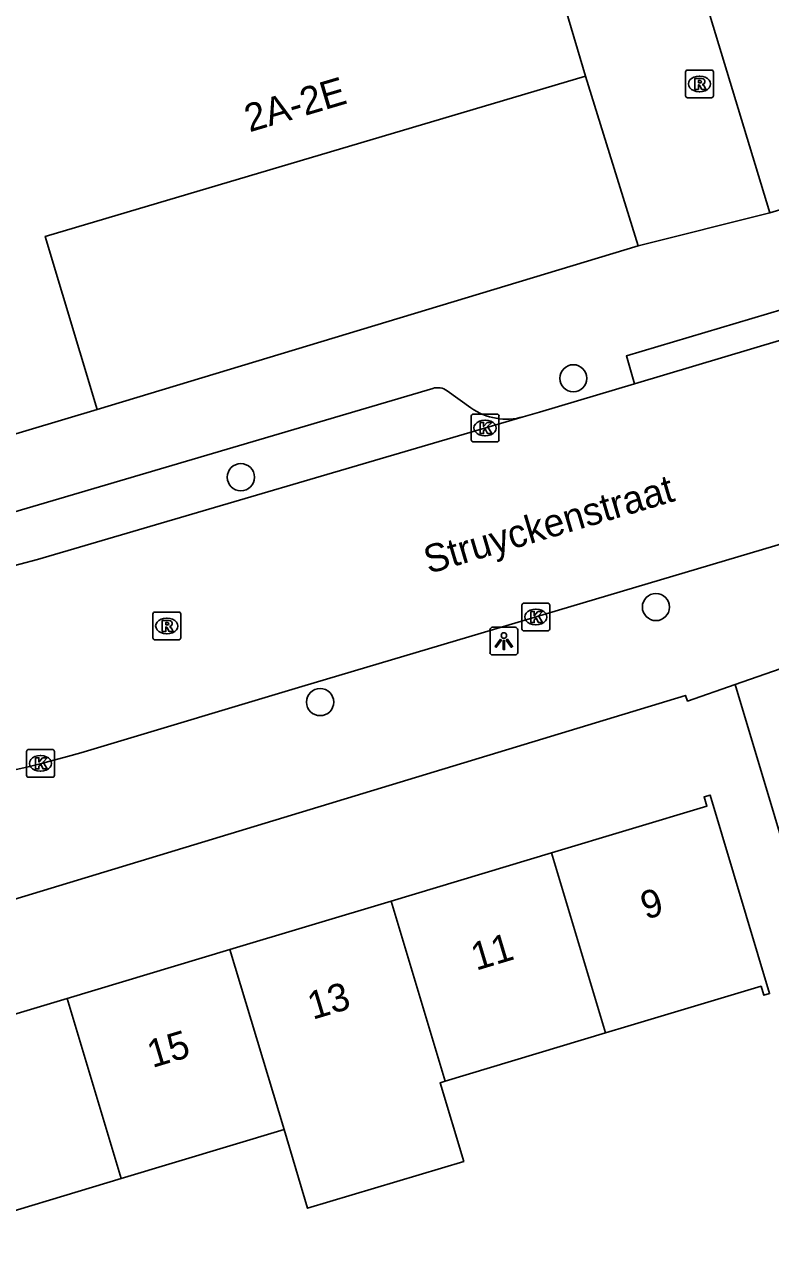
# Model space of a CAD drawing. Extents: x 158087 to 159494, y 382905 to 383981.
# Drawn here: x 158923.32 to 158950.15, y 383337.43 to 383381.71 of the extents above; entities that cross this region are included whole.
import ezdxf

# ---------------------------------------------------------------- set-up
doc = ezdxf.new("R2010")
doc.units = 0
for name, color, linetype in [('IMGEO_Boom', 7, 'Continuous'), ('IMGEO_Kolk', 7, 'Continuous'), ('IMGEO_Lichtpunt', 7, 'Continuous'), ('IMGEO_Openbare_ruimte_label', 7, 'Continuous'), ('IMGEO_Pand', 7, 'Continuous'), ('IMGEO_Pand_nummerreeks', 7, 'Continuous'), ('IMGEO_Rijbaan_lokaal_open', 7, 'Continuous'), ('IMGEO_Rioolput', 7, 'Continuous'), ('IMGEO_Voetpad_open', 7, 'Continuous')]:
    doc.layers.add(name, color=color, linetype=linetype)

msp = doc.modelspace()

# ---------------------------------------------------------------- linework, layer by layer
at = {"layer": 'IMGEO_Boom'}
for centre in [(158943.061, 383368.996), (158931.099, 383365.439), (158946.033, 383360.773), (158933.949, 383357.357)]:
    msp.add_circle(centre, 0.489, dxfattribs=at)
at = {"layer": 'IMGEO_Kolk'}
for p, q in [((158939.385, 383366.785), (158939.385, 383367.637)), ((158939.46, 383367.711), (158940.312, 383367.711)), ((158939.873, 383367.491), (158939.898, 383367.491)), ((158940.386, 383367.637), (158940.386, 383366.785)), ((158939.896, 383366.931), (158939.871, 383366.931)), ((158940.312, 383366.711), (158939.46, 383366.711)), ((158941.211, 383359.988), (158941.211, 383360.84)), ((158941.286, 383360.914), (158942.138, 383360.914)), ((158941.699, 383360.694), (158941.724, 383360.694)), ((158942.212, 383360.84), (158942.212, 383359.988)), ((158942.138, 383359.914), (158941.286, 383359.914)), ((158941.722, 383360.134), (158941.697, 383360.134)), ((158923.389, 383354.726), (158923.389, 383355.578)), ((158923.464, 383355.652), (158924.316, 383355.652)), ((158923.877, 383355.432), (158923.902, 383355.432)), ((158924.39, 383355.578), (158924.39, 383354.726)), ((158924.316, 383354.652), (158923.464, 383354.652)), ((158923.9, 383354.872), (158923.875, 383354.872))]:
    msp.add_line(p, q, dxfattribs=at)
for points in [[(158939.385, 383366.785), (158939.385, 383367.637)], [(158939.46, 383367.711), (158940.312, 383367.711)], [(158939.706, 383367.411), (158939.829, 383367.411), (158939.829, 383367.26), (158939.959, 383367.411), (158940.123, 383367.411), (158939.977, 383367.26), (158940.13, 383367.011), (158939.978, 383367.011), (158939.893, 383367.175), (158939.829, 383367.108), (158939.829, 383367.011), (158939.706, 383367.011), (158939.706, 383367.411)], [(158940.386, 383367.637), (158940.386, 383366.785)], [(158940.312, 383366.711), (158939.46, 383366.711)], [(158941.211, 383359.988), (158941.211, 383360.84)], [(158941.286, 383360.914), (158942.138, 383360.914)], [(158942.212, 383360.84), (158942.212, 383359.988)], [(158941.532, 383360.614), (158941.655, 383360.614), (158941.655, 383360.463), (158941.785, 383360.614), (158941.949, 383360.614), (158941.803, 383360.463), (158941.956, 383360.214), (158941.804, 383360.214), (158941.719, 383360.378), (158941.655, 383360.311), (158941.655, 383360.214), (158941.532, 383360.214), (158941.532, 383360.614)], [(158942.138, 383359.914), (158941.286, 383359.914)], [(158923.389, 383354.726), (158923.389, 383355.578)], [(158923.464, 383355.652), (158924.316, 383355.652)], [(158924.39, 383355.578), (158924.39, 383354.726)], [(158923.71, 383355.352), (158923.833, 383355.352), (158923.833, 383355.201), (158923.963, 383355.352), (158924.127, 383355.352), (158923.981, 383355.201), (158924.134, 383354.952), (158923.982, 383354.952), (158923.897, 383355.116), (158923.833, 383355.049), (158923.833, 383354.952), (158923.71, 383354.952), (158923.71, 383355.352)], [(158924.316, 383354.652), (158923.464, 383354.652)]]:
    msp.add_lwpolyline(points, dxfattribs=at)
for centre, start, end in [((158939.462, 383367.635), 91.552, 178.448), ((158939.462, 383367.635), 91.552, 178.448), ((158940.31, 383367.635), 1.552, 88.448), ((158940.31, 383367.635), 1.552, 88.448), ((158939.462, 383366.787), 181.552, 268.448), ((158939.462, 383366.787), 181.552, 268.448), ((158940.31, 383366.787), 271.552, 358.448), ((158940.31, 383366.787), 271.552, 358.448), ((158941.288, 383360.838), 91.552, 178.448), ((158941.288, 383360.838), 91.552, 178.448), ((158942.136, 383360.838), 1.552, 88.448), ((158942.136, 383360.838), 1.552, 88.448), ((158941.288, 383359.99), 181.552, 268.448), ((158941.288, 383359.99), 181.552, 268.448), ((158942.136, 383359.99), 271.552, 358.448), ((158942.136, 383359.99), 271.552, 358.448), ((158923.466, 383355.576), 91.552, 178.448), ((158923.466, 383355.576), 91.552, 178.448), ((158924.314, 383355.576), 1.552, 88.448), ((158924.314, 383355.576), 1.552, 88.448), ((158923.466, 383354.728), 181.552, 268.448), ((158923.466, 383354.728), 181.552, 268.448), ((158924.314, 383354.728), 271.552, 358.448), ((158924.314, 383354.728), 271.552, 358.448)]:
    msp.add_arc(centre, 0.0765, start, end, dxfattribs=at)
for centre, major_axis, ratio, start_param, end_param in [((158939.872, 383367.211), (-0.387, 0.002), 0.722429, 4.712389, 7.853982), ((158939.897, 383367.211), (-0.39, 0.002), 0.717154, 1.570796, 4.712389), ((158941.698, 383360.414), (-0.387, 0.002), 0.722429, 4.712389, 7.853982), ((158941.723, 383360.414), (-0.39, 0.002), 0.717154, 1.570796, 4.712389), ((158923.876, 383355.152), (-0.387, 0.002), 0.722429, 4.712389, 7.853982), ((158923.901, 383355.152), (-0.39, 0.002), 0.717154, 1.570796, 4.712389)]:
    msp.add_ellipse(centre, major_axis=major_axis, ratio=ratio, start_param=start_param, end_param=end_param, dxfattribs=at)
at = {"layer": 'IMGEO_Lichtpunt'}
for p, q in [((158940.063, 383359.951), (158940.063, 383359.144)), ((158940.063, 383359.951), (158940.063, 383359.144)), ((158940.965, 383360.046), (158940.157, 383360.046)), ((158940.965, 383360.046), (158940.157, 383360.046)), ((158941.059, 383359.144), (158941.059, 383359.951)), ((158941.059, 383359.144), (158941.059, 383359.951)), ((158940.157, 383359.05), (158940.965, 383359.05)), ((158940.157, 383359.05), (158940.965, 383359.05))]:
    msp.add_line(p, q, dxfattribs=at)
for points in [[(158940.437, 383359.615), (158940.476, 383359.587), (158940.288, 383359.325), (158940.25, 383359.352), (158940.437, 383359.615)], [(158940.539, 383359.567), (158940.586, 383359.567), (158940.586, 383359.245), (158940.539, 383359.245), (158940.539, 383359.567)], [(158940.649, 383359.587), (158940.687, 383359.614), (158940.874, 383359.352), (158940.835, 383359.324), (158940.649, 383359.587)]]:
    msp.add_lwpolyline(points, dxfattribs=at)
msp.add_circle((158940.562, 383359.749), 0.0994, dxfattribs=at)
for centre, start, end in [((158940.157, 383359.951), 90, 180), ((158940.157, 383359.951), 90, 180), ((158940.965, 383359.951), 0, 90), ((158940.965, 383359.951), 0, 90), ((158940.157, 383359.144), 180, 270), ((158940.157, 383359.144), 180, 270), ((158940.965, 383359.144), 270, 0), ((158940.965, 383359.144), 270, 360)]:
    msp.add_arc(centre, 0.0946, start, end, dxfattribs=at)
at = {"layer": 'IMGEO_Pand'}
for points in [[(158939.766, 383392.44), (158943.494, 383379.853)], [(158943.494, 383379.853), (158924.06, 383374.095), (158925.931, 383367.872)], [(158925.931, 383367.872), (158920.898, 383366.383)], [(158944.22, 383345.462), (158945.027, 383345.704), (158949.815, 383347.142), (158949.912, 383346.816), (158950.122, 383346.879), (158947.978, 383354.013), (158947.768, 383353.95), (158947.869, 383353.615), (158942.276, 383351.935)], [(158942.276, 383351.935), (158936.511, 383350.204)], [(158942.276, 383351.935), (158944.22, 383345.462)], [(158936.511, 383350.204), (158930.706, 383348.461)], [(158938.455, 383343.73), (158936.511, 383350.204)], [(158930.706, 383348.461), (158924.849, 383346.702)], [(158932.651, 383341.987), (158930.706, 383348.461)], [(158924.849, 383346.702), (158919.041, 383344.958)], [(158924.849, 383346.702), (158926.794, 383340.229)], [(158938.455, 383343.73), (158944.22, 383345.462)], [(158932.651, 383341.987), (158933.502, 383339.156), (158939.116, 383340.842), (158938.266, 383343.673), (158938.455, 383343.73)], [(158926.794, 383340.229), (158932.651, 383341.987)], [(158920.986, 383338.484), (158926.794, 383340.229)]]:
    msp.add_lwpolyline(points, dxfattribs=at)
at = {"layer": 'IMGEO_Rijbaan_lokaal_open'}
for points in [[(158942.233, 383428.468), (158944.391, 383393.87), (158950.13, 383374.942)], [(158943.494, 383379.853), (158945.392, 383373.761)], [(158950.13, 383374.942), (158945.392, 383373.761)], [(158980.272, 383371.894), (158974.99, 383370.288), (158953.096, 383363.795), (158933.294, 383357.916), (158925.825, 383355.673)], [(158953.723, 383371.321), (158945.266, 383368.803)], [(158941.259, 383367.613), (158941.839, 383367.783), (158945.266, 383368.803)], [(158919.464, 383361.557), (158921.866, 383361.978), (158923.788, 383362.481), (158941.259, 383367.613)]]:
    msp.add_lwpolyline(points, dxfattribs=at)
msp.add_arc((158912.536, 383400.116), 46.387, 266.7816, 286.6469, dxfattribs=at)
at = {"layer": 'IMGEO_Rioolput'}
for p, q in [((158947.099, 383379.154), (158947.099, 383380.006)), ((158947.174, 383380.08), (158948.026, 383380.08)), ((158947.587, 383379.86), (158947.612, 383379.86)), ((158948.1, 383380.006), (158948.1, 383379.154)), ((158947.61, 383379.3), (158947.585, 383379.3)), ((158948.026, 383379.08), (158947.174, 383379.08)), ((158927.933, 383359.667), (158927.933, 383360.519)), ((158928.008, 383360.593), (158928.86, 383360.593)), ((158928.421, 383360.373), (158928.446, 383360.373)), ((158928.934, 383360.519), (158928.934, 383359.667)), ((158928.444, 383359.813), (158928.419, 383359.813)), ((158928.86, 383359.593), (158928.008, 383359.593))]:
    msp.add_line(p, q, dxfattribs=at)
for points in [[(158947.099, 383379.154), (158947.099, 383380.006)], [(158947.174, 383380.08), (158948.026, 383380.08)], [(158947.688, 383379.778), (158947.436, 383379.78), (158947.436, 383379.38)], [(158948.1, 383380.006), (158948.1, 383379.154)], [(158947.436, 383379.38), (158947.56, 383379.38), (158947.56, 383379.542), (158947.571, 383379.542)], [(158947.614, 383379.699), (158947.56, 383379.699), (158947.56, 383379.618)], [(158947.56, 383379.618), (158947.612, 383379.618)], [(158947.618, 383379.513), (158947.689, 383379.38), (158947.829, 383379.38), (158947.764, 383379.506)], [(158948.026, 383379.08), (158947.174, 383379.08)], [(158927.933, 383359.667), (158927.933, 383360.519)], [(158928.008, 383360.593), (158928.86, 383360.593)], [(158928.522, 383360.291), (158928.27, 383360.293), (158928.27, 383359.893)], [(158928.934, 383360.519), (158928.934, 383359.667)], [(158928.27, 383359.893), (158928.394, 383359.893), (158928.394, 383360.055), (158928.405, 383360.055)], [(158928.448, 383360.212), (158928.394, 383360.212), (158928.394, 383360.131)], [(158928.394, 383360.131), (158928.446, 383360.131)], [(158928.452, 383360.026), (158928.523, 383359.893), (158928.663, 383359.893), (158928.598, 383360.019)], [(158928.86, 383359.593), (158928.008, 383359.593)]]:
    msp.add_lwpolyline(points, dxfattribs=at)
for centre, radius, start, end in [((158947.176, 383380.004), 0.0765, 91.552, 178.448), ((158947.176, 383380.004), 0.0765, 91.552, 178.448), ((158947.687, 383379.668), 0.109, 350.3612, 89.416), ((158948.024, 383380.004), 0.0765, 1.552, 88.448), ((158948.024, 383380.004), 0.0765, 1.552, 88.448), ((158947.57, 383379.489), 0.0533, 26.0293, 88.6989), ((158947.596, 383379.807), 0.19, 274.7715, 282.9687), ((158947.62, 383379.603), 0.0964, 77.0061, 93.1865), ((158947.634, 383379.66), 0.0378, 276.6634, 79.6772), ((158947.685, 383379.668), 0.112, 277.5842, 350.9817), ((158947.669, 383379.453), 0.108, 29.5134, 73.7905), ((158947.176, 383379.156), 0.0765, 181.552, 268.448), ((158947.176, 383379.156), 0.0765, 181.552, 268.448), ((158948.024, 383379.156), 0.0765, 271.552, 358.448), ((158948.024, 383379.156), 0.0765, 271.552, 358.448), ((158928.01, 383360.517), 0.0765, 91.552, 178.448), ((158928.01, 383360.517), 0.0765, 91.552, 178.448), ((158928.521, 383360.181), 0.109, 350.3612, 89.416), ((158928.858, 383360.517), 0.0765, 1.552, 88.448), ((158928.858, 383360.517), 0.0765, 1.552, 88.448), ((158928.404, 383360.002), 0.0533, 26.0293, 88.6989), ((158928.43, 383360.32), 0.19, 274.7715, 282.9687), ((158928.454, 383360.116), 0.0964, 77.0061, 93.1865), ((158928.468, 383360.173), 0.0378, 276.6634, 79.6772), ((158928.519, 383360.181), 0.112, 277.5842, 350.9817), ((158928.503, 383359.966), 0.108, 29.5134, 73.7905), ((158928.01, 383359.669), 0.0765, 181.552, 268.448), ((158928.01, 383359.669), 0.0765, 181.552, 268.448), ((158928.858, 383359.669), 0.0765, 271.552, 358.448), ((158928.858, 383359.669), 0.0765, 271.552, 358.448)]:
    msp.add_arc(centre, radius, start, end, dxfattribs=at)
for centre, major_axis, ratio, start_param, end_param in [((158947.586, 383379.58), (-0.387, 0.002), 0.722429, 4.712389, 7.853982), ((158947.611, 383379.58), (-0.39, 0.002), 0.717154, 1.570796, 4.712389), ((158928.42, 383360.093), (-0.387, 0.002), 0.722429, 4.712389, 7.853982), ((158928.445, 383360.093), (-0.39, 0.002), 0.717154, 1.570796, 4.712389)]:
    msp.add_ellipse(centre, major_axis=major_axis, ratio=ratio, start_param=start_param, end_param=end_param, dxfattribs=at)
at = {"layer": 'IMGEO_Voetpad_open'}
for points in [[(158966.914, 383379.966), (158950.13, 383374.942)], [(158945.392, 383373.761), (158925.931, 383367.872)], [(158945.266, 383368.803), (158944.969, 383369.8), (158953.426, 383372.318), (158953.723, 383371.321)], [(158921.201, 383363.675), (158938.004, 383368.635)], [(158938.521, 383368.547), (158939.375, 383367.937)], [(158950.507, 383358.546), (158948.88, 383357.985)], [(158909.091, 383346.657), (158910.089, 383346.37), (158947.093, 383357.596), (158947.173, 383357.395), (158948.88, 383357.985)], [(158948.88, 383357.985), (158954.631, 383338.838), (158954.089, 383335.82), (158952.374, 383334.556), (158952.414, 383325.208), (158952.223, 383325.192)]]:
    msp.add_lwpolyline(points, dxfattribs=at)
for centre, radius, start, end in [((158938.173, 383368.065), 0.595, 54.1852, 106.495), ((158940.652, 383369.721), 2.194, 234.4156, 286.0685)]:
    msp.add_arc(centre, radius, start, end, dxfattribs=at)

# ---------------------------------------------------------------- texts
at = {"layer": 'IMGEO_Openbare_ruimte_label'}
msp.add_text('Struyckenstraat', height=1, rotation=16.4962, dxfattribs=at).set_placement((158937.856, 383361.959))
at = {"layer": 'IMGEO_Pand_nummerreeks'}
for s, rotation, p in [('2A-2E', 16.5012, (158931.408, 383377.837)), ('9', 16.7153, (158945.664, 383349.528)), ('11', 16.7153, (158939.563, 383347.696)), ('13', 16.7132, (158933.684, 383345.931)), ('15', 16.7153, (158927.914, 383344.198))]:
    msp.add_text(s, height=1, rotation=rotation, dxfattribs=at).set_placement(p)

doc.saveas('drawing.dxf')
